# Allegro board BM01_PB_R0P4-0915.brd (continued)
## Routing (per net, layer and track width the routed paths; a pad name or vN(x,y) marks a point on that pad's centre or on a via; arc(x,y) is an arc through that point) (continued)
VCC5-20V_SYS: length 1.8
  BOTTOM w0.203: R623.2 26.99,2.69 27.42,3.12 v4(27.42,4.14)
  vias: v5(26.51,7.89) v5(26.51,7.25) v5(27.12,7.89) v5(27.12,7.25) v5(27.73,7.89) v5(27.73,7.25)
VCC5-20V_SYS_X1: length 5.5
  TOP w0.254: v1(23.83,14.24) 23.78,14.19 R701.1 23.63,14.19 v1(23.58,14.24)
  GND2 w0.254: v1(27.42,13.69) v1(27.17,13.69) 26.99,13.69 v2(26.86,13.56) ; v2(23.98,13.93) 23.83,14.07 v1(23.83,14.24) v1(23.58,14.24)
  GND5 w0.254: v3(26.27,13.51) v3(26.52,13.51) 26.81,13.51 v2(26.86,13.56) ; v2(23.98,13.93) 24.09,13.81 v3(24.09,13.51) v3(23.84,13.51)
  BOTTOM w0.254: v3(23.84,13.51) v3(24.09,13.51) v3(26.27,13.51) v3(26.52,13.51)
VCC5-20V_SYS_X2: length 4.8
  TOP w0.254: C712.1 16.24,5.21 15.98,4.95 R709.1 ; v1(12.83,6.88) v1(12.83,7.13) 12.88,7.19 R706.1
  GND2 w0.254: v2(13.15,6.97) 13.06,6.88 v1(12.83,6.88) v1(12.83,7.13) ; v1(15.9,6.81) v1(15.65,6.81) 15.59,6.75 v2(15.33,6.75)
  SIG4 w0.254: v2(15.33,6.75) 15.1,6.75 14.67,7.19 13.36,7.19 v2(13.15,6.97)
VCC5-20V_SYS_X3: length 8.3
  TOP w0.254: R710.1 v1(18.04,15.53) v1(17.79,15.53)
  GND2 w0.254: v2(22.08,14.49) 22.04,14.54 v1(21.76,14.54) v1(21.51,14.54) ; v1(17.79,15.53) v1(18.04,15.53) 18.19,15.53 18.21,15.54 v2(18.36,15.54)
  SIG3 w0.254: v2(22.08,14.49) 22,14.58 21.07,14.58 20.81,14.83 20.81,15.6 20.06,16.35 19.31,16.35 18.5,15.54 v2(18.36,15.54)
  GND5 w0.254: v3(22.41,14.96) v3(22.24,14.78) 22.08,14.63 v2(22.08,14.49)
  BOTTOM w0.254: R714.1 22.5,15.04 v3(22.41,14.96) v3(22.24,14.78)
VCC_0V9:
  vias: v5(14.8,18.56) v5(15.44,18.56) v5(16.07,18.56) v5(35.65,18.6) v5(36.26,18.6)
VCC_0V9_X1: length 5.6
  TOP w0.254: 18.29,18.02 17.04,16.77 17.04,14.58 18.12,13.5 R711.2
VCC_0V9_X2: length 5.9
  TOP w0.254: C722.2 v1(18.27,16.13) v1(18.02,16.13)
  GND2 w0.254: v2(21.4,15.19) 21.52,15.07 v1(21.72,15.07) v1(21.97,15.07) ; v1(18.02,16.13) v1(18.27,16.13) v2(18.27,16.46)
  SIG4 w0.254: v2(18.27,16.46) 18.68,16.87 20.24,16.87 21.4,15.72 v2(21.4,15.19)
VCC_3V3_SYS1: length 88.5
  TOP w0.254: v4(50.05,13.28) 50.05,12.93 48.73,11.61 45.86,11.61 45.25,12.22 R1112.1
  SIG3 w0.254: v5(37.17,19.54) 37.82,19.54 42.53,14.83 47.94,14.83 48.65,14.12 49.21,14.12 v4(50.05,13.28) 50.05,12.95 49.35,12.25 49.35,7.05 47.54,5.23 44.61,5.23 43.17,3.78 40.87,3.78 39.86,4.79 39.86,5.18 39.58,5.47 v2(39.14,5.47) 38.8,5.81 37.74,5.81 36.89,6.67 36.89,7.9 35.03,9.76 28.51,9.76 v2(28.11,9.37)
  SIG3 w0.305: v4(6.25,15.65) 6.88,15.02 v4(9.42,15.02)
  SIG4 w0.254: v2(22.85,16.43) 22.85,16.63 21.91,17.57 21.91,20.11 22.06,20.27 v5(22.06,20.53) v5(21.43,20.53)
  SIG4 w0.305: v5(21.43,20.53) 21.13,20.53 20.89,20.29 12.69,20.29 10.07,17.67 10.07,15.47 9.62,15.02 v4(9.42,15.02)
  GND5 w0.254: v3(23.06,16.03) 22.9,16.03 22.83,16.1 v3(22.82,16.1) 22.82,16.4 v2(22.85,16.43)
  GND5 w0.305: v3(38.81,5.47) v2(39.14,5.47) ; v3(28.11,9.95) v3(28.11,9.7) v2(28.11,9.37)
  BOTTOM w0.254: C804.1 v4(6.25,15.65) ; C804.1 R801.2 R803.1 ; C804.1 6.71,16.22 6.81,16.32 U801.A3 ; R525.1 v3(38.81,5.47) R524.1 ; R802.1 v4(9.42,15.02) ; v3(22.82,16.1) 22.89,16.03 v3(23.06,16.03) R908.1
  BOTTOM w0.305: R518.1 27.19,12.19 27.37,12.19 27.57,11.99 27.33,11.75 R526.1 27.13,11.72 26.83,11.41 26.83,10.21 27.45,9.59 28,9.59 v3(28.11,9.7) v3(28.11,9.95) R527.1
  vias: v5(36.56,19.54)
VCC_3V3_SYS1_X1: length 8.1
  TOP w0.254: R703.2 23.59,11.61 22.86,12.34 v1(22.86,13.42) v1(22.86,13.67)
  GND2 w0.254: v1(22.86,13.42) v1(22.86,13.67) 23.09,13.9 v2(23.1,13.9) ; v1(24.88,16.47) v1(25.13,16.47) v2(25.13,16.14)
  SIG3 w0.254: v2(25.13,16.14) 25.13,15.11 24.58,14.56 23.47,14.56 23.1,14.2 v2(23.1,13.9)
VCC_3V3_SYS1_X2: length 5.5
  TOP w0.254: v1(24.11,15.36) 24.35,15.36 C704.2
  GND2 w0.254: v2(26.91,14.5) 27.09,14.32 v1(27.19,14.32) v1(27.44,14.32) ; v1(24.36,15.36) v1(24.11,15.36) 24.11,15.08 v2(24.06,15.03)
  GND5 w0.254: v2(26.91,14.5) 26.86,14.5 v3(26.66,14.3) v3(26.4,14.3) ; v2(24.06,15.03) 24.07,15.02 v3(24.07,14.69) 24.07,14.6 v3(24.2,14.47)
  BOTTOM w0.254: v3(26.66,14.3) v3(26.4,14.3) 24.38,14.3 v3(24.2,14.47) 24.07,14.6 v3(24.07,14.69)
VDD12:
  vias: v5(12.85,18.56) v5(13.16,18.04) v5(13.48,18.56) v5(33.55,19.49) v5(34.16,19.49) v5(34.77,19.49)
VDD12_BST: length 1.1
  TOP w0.254: C713.1 13.77,8.11 14.06,7.81 U702.5
VDD12_EN: length 1.6
  TOP w0.254: U702.6 13.96,7.31 13.62,7.65 C716.1 R706.2
VDD12_FB: length 1.8
  TOP w0.254: U702.8 14.25,6.31 14,6.06 R708.2 R707.1
VDD12_PG: length 0.9
  TOP w0.254: U702.1 15.78,5.81 15.75,5.78 R709.2
VDD12_SS: length 1.2
  TOP w0.254: U702.7 13.98,6.81 13.44,6.28 C718.1
VDD12_X1: length 6.8
  TOP w0.254: 13.54,10.45 13.13,10.45 11.57,8.89 11.57,6.67 R707.2
VDD12_X2: length 5.1
  TOP w0.254: v1(12.34,7.72) 12.34,7.72 v1(12.52,7.91) 12.72,8.11 C713.2
  GND2 w0.254: v2(12.27,7.39) 12.27,7.65 v1(12.34,7.72) 12.34,7.72 v1(12.52,7.91) ; v1(15.9,7.36) v1(15.65,7.36) 15.35,7.36 v2(15.32,7.36)
  SIG3 w0.254: v2(12.27,7.39) 12.43,7.55 15.13,7.55 v2(15.32,7.36)
90_BILLBOARD_DN_X1: length 8.5
  SIG3 w0.089: v4(4.27,11.22) 4.11,11.38 3.88,11.38 3.67,11.59 3.67,12.07 4.01,12.41 5.12,12.41 5.83,11.71 6.02,11.71 v4(6.15,11.83)
  BOTTOM w0.102: J801.A7 5.63,11.75 5.77,11.61 5.93,11.61 v4(6.15,11.83) 6.29,11.68 6.97,11.68 7.04,11.75 7.32,11.75 TVS806.2 7.58,11.73 7.8,11.73 R810.2 ; v4(4.27,11.22) 4.74,10.75 J801.B7
90_BILLBOARD_DN_X2: length 36.9
  TOP w0.102: J1002.11 34.61,4.2 34.51,4.1 34.31,4.1 34.21,4.2 v4(34.21,4.31)
  SIG3 w0.089: v4(8.94,11.93) 8.94,11.82 9.03,11.73 9.35,11.73 9.65,11.43 9.65,5.55 10.8,4.4 17.69,4.4 19.86,2.23 33.1,2.23 33.63,2.76 33.63,3.89 33.84,4.1 34.01,4.1 v4(34.21,4.31)
  BOTTOM w0.102: R810.1 8.56,11.73 8.74,11.73 v4(8.94,11.93)
90_BILLBOARD_DP_X1: length 8.5
  SIG3 w0.089: v4(6.15,11.22) 6.15,11.32 5.96,11.5 5.74,11.5 5.57,11.68 5.44,11.68 5.37,11.61 5.24,11.61 5.12,11.73 5.12,11.86 5.19,11.93 5.19,12.06 5.04,12.21 4.09,12.21 3.87,11.99 3.87,11.67 3.96,11.58 4.16,11.58 4.27,11.68 v4(4.27,11.83)
  BOTTOM w0.102: J801.B6 4.69,12.25 v4(4.27,11.83) ; J801.A6 5.63,11.25 5.79,11.41 5.96,11.41 v4(6.15,11.22) 6.4,11.48 7.06,11.48 7.12,11.55 7.28,11.55 TVS805.2 7.58,11.53 7.8,11.53 R811.2
90_BILLBOARD_DP_X2: length 36.9
  TOP w0.102: v4(34.21,3.7) 34.21,3.8 34.31,3.9 34.51,3.9 34.61,3.8 J1002.12
  SIG3 w0.089: v4(8.94,11.32) 9.14,11.53 9.27,11.53 9.45,11.35 9.45,5.47 10.72,4.2 17.6,4.2 19.78,2.02 33.18,2.02 33.84,2.67 33.84,3.81 33.93,3.9 34.08,3.9 34.21,3.77 v4(34.21,3.7)
  BOTTOM w0.102: v4(8.94,11.32) 8.74,11.53 8.56,11.53 R811.1
C_PD_ADA_VBUS1: length 0.9
  TOP w0.254: v5(8.38,8.12) R1001.2
  vias: v5(3.61,14.27) v5(3.61,13.64) v5(3.61,9.63) v5(3.61,9) v5(4.24,14.27) v5(4.24,13.64) v5(4.24,9.63) v5(4.24,9) v5(6.48,8.73) v5(6.48,8.12) v5(7.11,8.73) v5(7.11,8.12) v5(7.75,8.73) v5(7.75,8.12) v5(8.38,8.73)
CHARGE_OC: length 31.9
  GND2 w0.109: v1(31.82,5.88) 31.88,5.81 v2(32.14,5.81)
  SIG4 w0.109: v2(32.14,5.81) 32.76,6.44 35.38,6.44 35.75,6.8 35.75,14.3 38.15,16.7 38.15,19.9 37.35,20.71 25.68,20.71 v2(25.46,20.93)
  GND5 w0.109: v2(25.46,20.93) 25.43,20.96 v3(25.13,20.96)
CHARGE_PE1: length 36.1
  GND2 w0.109: v1(30.81,5.94) 30.94,5.81 v2(31.12,5.81)
  SIG4 w0.109: v2(31.12,5.81) 31.97,6.67 35.29,6.67 35.52,6.9 35.52,14.39 37.92,16.79 37.92,19.8 37.25,20.47 30.31,20.47 26.5,16.66 v2(24.19,16.66)
  GND5 w0.109: v2(24.19,16.66) 24.24,16.61 v3(24.52,16.61)
  BOTTOM w0.254: R902.2 24.75,16.79 24.86,16.9 U901.1
CHG_CC1: length 40.3
  TOP w0.305: J1002.9 35.61,4.5 v4(35.39,4.28)
  SIG3 w0.305: v4(35.39,4.28) 34.77,4.9 23.99,4.9 20.57,8.32 12.16,8.32 10.89,9.59 10.89,14.81 9.21,16.49 v4(5.74,16.49)
  BOTTOM w0.254: v4(5.74,16.49) 6.32,16.49 6.67,16.85 U801.A2
CHG_CC2: length 42.9
  TOP w0.305: J1002.7 36.61,4.89 36.27,4.55 v4(36.16,4.55)
  SIG3 w0.305: v4(6.53,17.69) 6.53,18.08 7.15,18.69 9.91,18.69 11.32,17.28 11.32,9.77 12.34,8.75 20.75,8.75 24.17,5.33 35.38,5.33 v4(36.16,4.55)
  GND5 w0.254: v3(7.21,16.85) 7.01,17.05 7.01,17.26 6.58,17.69 v4(6.53,17.69)
CHG_VBUS_MON: length 32.9
  TOP w0.254: v1(11.87,5.41) v1(11.62,5.41) 9.87,5.41 8.9,6.38 R1001.1 R1002.2
  TOP w0.381: J1002.5 37.61,4.83 36.95,4.17 v4(36.6,4.17)
  GND2 w0.254: v1(11.62,5.41) v1(11.87,5.41) 12.03,5.57 v2(12.03,5.7)
  SIG4 w0.305: v2(12.03,5.7) 12.21,5.52 22.71,5.52 23.16,5.08 36.38,5.08 36.69,4.77 36.69,4.25 v4(36.6,4.17)
DSP_AUX_CTR: length 3.1
  BOTTOM w0.175: U801.D3 8.43,16.04 C805.1 R804.1 R802.2 R809.1 8.55,14.42 Q801.3
DSP_CC1_X1: length 15.5
  SIG4 w0.254: v4(6.17,17) 6.2,16.98 6.2,16.35 6.7,15.84 6.7,15.47 6.47,15.23 6.47,12.69 7.29,11.87 7.29,10.39 7.77,9.91 8.46,9.91 v2(8.84,10.3)
  GND5 w0.254: v2(8.84,10.3) v3(8.51,10.3) v3(8.51,10.04)
  BOTTOM w0.203: TP801.1 5.41,17.76 v4(6.17,17) 6.42,17.25 U801.A1
  BOTTOM w0.254: J801.A5 5.73,10.25 5.8,10.18 6.96,10.18 7.23,10.45 TVS807.2 8.35,10.45 v3(8.51,10.3) v3(8.51,10.04)
DSP_CC2_X1: length 12.4
  SIG4 w0.254: v2(6.96,13.83) 6.85,13.94 6.85,15.07 7.01,15.24 7.32,15.24 7.74,14.82 8.01,14.82 8.2,15.01 8.2,16.66 8.01,16.85 7.65,16.85 7.49,16.7 7.49,16.33 7.29,16.12 6.96,16.12 6.63,16.46 6.63,17.14 7.02,17.54 v4(7.02,17.89)
  GND5 w0.254: v2(6.96,13.83) 6.96,13.59 v3(6.88,13.51) 6.88,13.43 v3(6.74,13.29)
  BOTTOM w0.203: U801.B1 7.21,17.44 7.02,17.63 v4(7.02,17.89) 6.62,18.3 TP802.1
  BOTTOM w0.254: J801.B5 6.06,13.25 6.07,13.24 TVS802.2 6.69,13.24 v3(6.74,13.29) 6.88,13.43 v3(6.88,13.51)
DSP_SBU1_X1: length 13.6
  SIG4 w0.254: v2(7.96,10.37) 7.67,10.66 7.67,12.03 6.99,12.71 6.99,13.16 8.58,14.75 8.58,16.88 8.23,17.23 7.97,17.23 7.56,17.63 v4(7.56,17.69)
  GND5 w0.254: v2(7.96,10.37) 7.86,10.28 v3(7.86,10.06) v3(8.11,10.06)
  BOTTOM w0.203: U801.C1 7.56,17.3 v4(7.56,17.69)
  BOTTOM w0.254: J801.B8 6.03,9.75 6.09,9.8 7.13,9.8 7.23,9.91 TVS804.2 7.72,9.91 v3(7.86,10.06) v3(8.11,10.06) ; R807.1 v4(7.56,17.69)
DSP_SBU1_X2: length 2.3
  GND5 w0.254: v3(7.61,16.85) 7.61,17.02 8.16,17.57 v4(8.16,17.69)
  BOTTOM w0.254: v4(8.16,17.69) 8.38,17.92 R807.2 R812.2
DSP_SBU1_X3: length 39.4
  TOP w0.102: J1002.16 32.61,2.8 32.21,3.2 32.21,3.44 32.31,3.54 v4(32.42,3.54)
  SIG3 w0.089: v4(8.99,12.78) 9.13,12.92 9.35,12.92 10.13,12.15 10.13,9.28 10.46,8.94 10.46,5.84 11.45,4.86 18.38,4.86 20.55,2.69 31.83,2.69 32.26,3.12 32.26,3.38 v4(32.42,3.54)
  BOTTOM w0.102: v4(8.99,12.78) 9.17,12.96 9.52,12.96 10.04,13.48 10.04,17.37 9.77,17.64 9.77,17.85 9.5,18.12 R812.1
DSP_SBU2_X1: length 9.8
  SIG4 w0.254: v2(7.47,12.99) 8.96,14.48 8.96,17.3 9.32,17.66 v4(9.32,17.74)
  GND5 w0.254: v2(7.47,12.99) 7.47,12.94 v3(7.26,12.73) v3(7,12.73)
  BOTTOM w0.203: v4(9.32,17.74) 9.32,17.66 9.09,17.44 R808.1 8.6,17.44 8.41,17.25 U801.D1
  BOTTOM w0.254: J801.A8 5.78,12.75 5.88,12.85 6.31,12.85 6.41,12.76 TVS803.2 6.96,12.76 6.99,12.73 v3(7,12.73) v3(7.26,12.73)
DSP_SBU2_X2: length 1.7
  BOTTOM w0.175: U801.D2 8.28,16.85 8.51,16.62 R808.2 9.31,16.62 R813.2
DSP_SBU2_X3: length 39.3
  TOP w0.102: v4(31.81,3.54) 31.91,3.54 32.01,3.44 32.01,3.21 31.61,2.82 J1002.18
  SIG3 w0.089: v4(8.99,13.39) 8.99,13.28 9.14,13.13 9.44,13.13 10.33,12.23 10.33,9.36 10.67,9.03 10.67,8.77 10.76,8.69 10.81,8.69 10.9,8.6 10.9,8.42 10.81,8.33 10.76,8.33 10.67,8.24 10.67,8.06 10.76,7.97 10.81,7.97 10.9,7.88 10.9,7.71 10.81,7.62 10.76,7.62 10.67,7.53 10.67,7.35 10.76,7.26 10.81,7.26 10.9,7.17 10.9,7 10.81,6.91 10.76,6.91 10.67,6.82 10.67,6.64 10.76,6.55 10.81,6.55 10.9,6.46 10.9,6.28 10.81,6.2 10.76,6.2 10.67,6.11 10.67,5.93 11.53,5.06 18.47,5.06 20.63,2.9 31.74,2.9 32.05,3.21 32.05,3.46 31.97,3.54 v4(31.81,3.54)
  BOTTOM w0.102: R813.1 9.5,17.27 9.6,17.37 9.75,17.37 9.84,17.28 9.84,13.57 9.44,13.16 9.09,13.16 8.99,13.26 v4(8.99,13.39)
EN2: length 2.6
  TOP w0.107: U1101.C1 43.2,13.96 43.64,13.52 R1111.2 R1110.2
GPIO1_ILIMT_2A: length 26.7
  TOP w0.107: v4(48.93,14.87) 48.93,14.37 47.44,12.88 46.57,12.88 R1105.2
  GND2 w0.127: v2(34.07,5.81) 34.01,5.81 v1(33.81,5.61)
  SIG4 w0.109: v2(34.07,5.81) 34.19,5.94 35.56,5.94 36.22,6.61 36.22,12.82 38.47,15.07 48.74,15.07 v4(48.93,14.87)
GPIO2_CHG_VBUS_DISCHARGE: length 41.3
  TOP w0.109: v4(38.35,3.87) 38.08,4.14 38.08,4.55 38.61,5.08 J1002.3
  SIG3 w0.109: v2(15.42,16.38) 15.28,16.52 13.11,16.52 12.13,15.55 12.13,10.1 12.68,9.55 21.09,9.55 24.5,6.14 29.7,6.14 30.23,6.67 35.31,6.67 38.12,3.87 v4(38.35,3.87)
  GND5 w0.109: v3(15.62,16.65) 15.42,16.45 v2(15.42,16.38)
  BOTTOM w0.109: R603.2 15.83,16.86 v3(15.62,16.65)
GPIO4_CHG_VBUS_CTRL: length 54
  TOP w0.109: v4(38.63,3.41) 38.61,3.4 J1002.4
  SIG3 w0.109: v4(38.63,3.41) 38.24,3.41 35.22,6.44 30.35,6.44 29.82,5.9 24.4,5.9 20.99,9.32 12.58,9.32 11.89,10 11.89,15.64 13.01,16.76 16.07,16.76 16.86,15.97 v2(17.35,15.97)
  SIG4 w0.109: v2(17.35,15.97) 17.35,16.57 17.03,16.89 12.84,16.89 10.44,14.49 v4(9.42,14.49)
  GND5 w0.109: v2(17.35,15.97) v3(17.68,15.97)
  BOTTOM w0.109: R604.2 17.88,15.77 v3(17.68,15.97) ; v4(9.42,14.49) 9.39,14.51 R809.2 R805.2
GPIO4_CTRL_X1: length 2.9
  BOTTOM w0.175: Q801.1 7.77,15.02 7.4,14.64 R803.2 R806.1 7.29,14 R805.1
GPIO5_PLUG_VBUS_DISCHARGE: length 65.5
  TOP w0.109: J1002.1 39.61,5.08 39.24,4.7 v4(38.52,4.38) ; R605.1 16.21,15.74 v1(16.16,15.79) ; v4(50.05,12.27) 50.05,12.09 49.26,11.3 45.5,11.3 R1109.1
  GND2 w0.109: v2(16.16,16.12) v1(16.16,15.79)
  SIG3 w0.109: v2(16.16,16.12) 16.02,15.97 15.2,15.97 14.89,16.29 13.21,16.29 12.37,15.45 12.37,10.2 12.78,9.79 21.18,9.79 24.6,6.37 29.55,6.37 30.09,6.91 35.41,6.91 37.93,4.38 v4(38.52,4.38) 38.69,4.56 39.66,4.56 40.76,3.45 43.42,3.45 44.79,4.82 47.64,4.82 49.66,6.85 49.66,11.88 v4(50.05,12.27)
GPIO6_PLUG_VBUS_CTRL: length 44.4
  TOP w0.109: v4(39.5,3.41) 39.61,3.3 J1002.2
  SIG3 w0.109: v2(16.87,16.5) 16.38,17 12.91,17 11.66,15.74 11.66,9.91 12.48,9.08 20.89,9.08 24.3,5.67 29.99,5.67 30.52,6.2 35.12,6.2 38.29,3.03 39.12,3.03 v4(39.5,3.41)
  GND5 w0.109: v3(16.81,16.83) 16.81,16.56 v2(16.87,16.5)
GPIO7_KS1865C_EN: length 32.2
  TOP w0.107: v1(34.12,1.64) 31.08,1.64 30.61,2.1 J1002.20 ; v4(50.05,10.23) 49.45,10.83 45,10.83 R1110.1
  GND2 w0.127: v1(34.12,1.64) v2(34.35,1.87)
  SIG4 w0.109: v2(34.35,1.87) 34.85,2.36 42.56,2.36 44.23,4.04 47.46,4.04 50.05,6.63 v4(50.05,10.23)
GPIO8_ILIMT_3A: length 27
  TOP w0.107: R1106.2 47.35,13.2 48.53,14.37 48.53,15.09 v4(48.93,15.49)
  GND2 w0.127: v1(32.78,5.61) 32.98,5.81 v2(33.04,5.81)
  SIG4 w0.109: v4(48.93,15.49) 48.74,15.3 38.33,15.3 35.99,12.96 35.99,6.7 35.48,6.2 33.42,6.2 v2(33.04,5.81)
HV_AGND1: length 5.4
  GND5 w0.254: v3(37.34,5.47) v3(37.59,5.47) 37.59,6.08 v2(37.86,6.35) ; v2(40.35,5.13) 40.29,5.19 40.29,5.42 v3(40.22,5.48) ; v3(40.35,12.39) v2(40.12,12.16)
  BOTTOM w0.254: U501.17 v3(40.35,12.39) ; R514.2 v3(37.34,5.47) v3(37.59,5.47) ; v4(42.6,6.03) 42.52,5.95 C512.2 R509.1 ; v4(42.6,6.59) 42.47,6.46 C511.1 R507.1 ; C510.1 41.07,13.9 40.87,14.11
  vias: v2(38.99,13.97) v2(39.27,14.26) v3(38.8,14.24) v3(38.98,14.41) v3(39.15,14.59) v3(39.4,14.57)
I2C0_SCL_X1: length 19.8
  TOP w0.109: J1002.8 v4(36.61,3.4)
  SIG3 w0.109: v2(28.79,9.28) 29.03,9.04 35.07,9.04 36.36,7.75 36.36,6.63 37.54,5.45 38.48,5.45 38.93,5 v2(39.41,5)
  SIG4 w0.109: v2(39.41,5) 39.39,5.01 38.29,5.01 37.62,4.33 37.62,3.25 37.39,3.02 36.99,3.02 v4(36.61,3.4)
  GND5 w0.127: v2(39.41,5) 39.62,5.21 v3(39.62,5.26) ; v3(28.61,9.59) 28.61,9.46 v2(28.79,9.28)
  BOTTOM w0.107: R520.2 v3(39.62,5.26) ; R523.1 v3(28.61,9.59)
I2C0_SDA_X1: length 17.6
  TOP w0.109: v4(37.23,3.41) 37.61,3.03 J1002.6
  SIG3 w0.109: v2(37.81,5.06) 37.59,5.06 36.11,6.55 36.11,7.67 34.97,8.8 28.13,8.8 27.42,9.51 v2(27.42,9.83)
  SIG4 w0.109: v4(37.23,3.41) 37.38,3.56 37.38,4.64 v2(37.81,5.06)
  GND5 w0.127: v3(27.7,9.99) 27.58,9.99 v2(27.42,9.83) ; v2(37.81,5.06) 38.08,5.34 v3(38.08,5.35)
  BOTTOM w0.107: v3(38.08,5.35) 38.1,5.36 R521.2 ; v3(27.7,9.99) 27.34,10.35 R522.1
MOUT: length 1.8
  BOTTOM w0.254: 21.25,7.26 21.14,7.16 R615.2 ; 18.36,9.54 18.17,9.54 R607.1
MOUT_ADC: length 8.2
  TOP w0.107: J1002.14 33.61,2.9 v1(33.31,3.2)
  GND2 w0.127: v2(33.03,3.04) 33.19,3.2 v1(33.31,3.2)
  GND5 w0.127: v2(33.03,3.04) v3(32.79,2.8)
  BOTTOM w0.107: R625.1 31.99,2 v3(32.79,2.8)
MT7231_DISCI: length 0.8
  BOTTOM w0.254: R620.2 21.56,4.65 21.68,4.78 U602.2
MT7231_DISCO: length 0.9
  BOTTOM w0.254: R616.2 21.46,5.31 21.52,5.38 U602.3
MT7231_EN: length 0.8
  BOTTOM w0.254: U602.4 R615.1
MT7231_FLTB: length 0.9
  BOTTOM w0.254: U602.9 24.57,6.58 24.92,6.23 R619.2
MT7231_ILIM: length 1.4
  BOTTOM w0.254: U602.11 24.61,5.38 24.77,5.21 C616.1 R621.2
MT7231_MOUT: length 8.3
  SIG3 w0.305: v2(25.49,6.89) 25.18,6.89 v4(23.41,8.66)
  GND5 w0.305: v2(25.49,6.89) v3(25.49,6.48) v3(25.49,6.23)
  BOTTOM w0.175: v4(23.41,8.66) 23.12,8.38 U602.7
  BOTTOM w0.203: U602.15 U602.7
  BOTTOM w0.254: v3(25.49,6.23) v3(25.49,6.48)
MT7231_NOSS: length 0.9
  BOTTOM w0.254: R617.2 21.41,3.99 21.59,4.18 U602.1
MT7231_VLIM: length 1.2
  BOTTOM w0.254: R622.2 24.96,4.28 24.47,4.78 U602.12
MT7232_DISC1: length 2.3
  TOP w0.254: v4(15.51,14.12) 15.51,14.01 15.91,13.61 R610.2 R605.2
  BOTTOM w0.254: U601.2 15.51,13.61 v4(15.51,14.12)
MT7232_DISC2: length 3.2
  BOTTOM w0.254: 16.13,13.96 U601.3
  BOTTOM w0.305: 16.13,13.96 16.03,14.06 R609.2 15.74,14.55 15.49,14.8 15.49,15.7 15.83,16.04 R603.1
MT7232_EN1: length 3.2
  BOTTOM w0.254: 16.73,13.97 U601.4
  BOTTOM w0.305: R606.2 17.04,16.04 17.33,15.75 17.33,14.78 17.1,14.55 R611.2 16.79,14.03 16.73,13.97
MT7232_EN2: length 2.2
  BOTTOM w0.254: U601.5 17.33,13.76
  BOTTOM w0.305: R608.2 R604.1 17.88,14.53 17.33,13.98 17.33,13.76
MT7232_FLTB: length 1
  BOTTOM w0.254: U601.9 17.33,11.08 17.66,10.74 R607.2
MT7232_ILIM1: length 1.4
  BOTTOM w0.254: R612.2 C607.1 16.03,10.81 16.13,10.91 U601.11
MT7232_ILIM2: length 1.5
  TOP w0.254: v4(14.98,14.12) R613.2 C608.1
  BOTTOM w0.254: v4(14.98,14.12) 14.98,14.11 14.93,14.05 U601.1
MT7232_VLIM: length 0.8
  BOTTOM w0.254: R614.2 U601.12
OVLO: length 1.5
  BOTTOM w0.254: U901.2 24.21,16.86 24.12,16.76 R904.1 R910.2
OVLO_17839094: length 1.7
  TOP w0.107: R1113.1 R1114.2 44.47,15.71 44.23,15.96 U1101.D5
PD_USP_VBUS: length 4.6
  TOP w0.254: v4(45.12,17.43) R1113.2
  GND2 w0.254: v2(42.68,16.79) v1(42.68,17.13) v1(42.68,17.38)
  SIG4 w0.254: v2(42.68,16.79) 44.68,16.79 45.12,17.23 v4(45.12,17.43)
PD_USP_VBUS_X1:
  vias: v5(13.09,15.18) v5(13.09,14.54) v5(13.09,13.91) v5(13.73,15.18) v5(13.73,14.54) v5(13.73,13.91) v5(30.14,13.94) v5(30.14,13.33) v5(30.75,13.94) v5(30.75,13.33) v5(31.36,13.94) v5(31.36,13.33)
PP5V0: length 2.3
  BOTTOM w0.254: v3(21.64,19.03) 21.22,18.61 R905.2
  vias: v2(22.72,19.77) v2(22.72,19.37) v2(23.12,19.77) v2(23.12,19.37) v2(25.72,18.88) v2(26.12,18.88) v2(26.54,19.29) v2(26.54,18.88) v3(21.64,19.53) v3(21.64,19.28) v3(21.89,19.53) v3(21.89,19.28) v3(21.89,19.03) v3(22.14,19.53) v3(22.14,19.28) v3(22.14,19.03) v3(22.39,19.53) v3(22.39,19.28) v3(22.39,19.03) v3(25.46,19.67) v3(25.46,19.42) v3(25.46,19.17) v3(25.71,19.71) v3(25.71,19.46) v3(25.71,19.21) v3(25.96,19.69) v3(25.96,19.44) v3(25.96,19.19) v3(26.21,19.7) v3(26.21,19.45) v3(26.21,19.2) v4(23.24,18.61) v4(23.82,18.61) v4(24.41,18.61) v4(24.99,18.61) v5(30.47,19.61) v5(30.47,19) v5(30.47,18.39) v5(31.08,19.61) v5(31.08,19) v5(31.08,18.39)
PP5V0_SYS: length 1.6
  SIG4 w0.254: 23.74,16.94 23.74,16.37 v2(23.86,16.24)
  GND5 w0.254: v2(23.86,16.24) 24.1,16 v3(24.12,16) v3(24.12,15.75)
  BOTTOM w0.254: v3(24.12,15.75) v3(24.12,16) R904.2
  vias: v2(22.86,17.62) v2(23.27,17.62) v2(25.27,18.1) v2(25.68,18.1) v2(26.09,18.1) v2(26.49,18.1) v3(21.79,18.05) v3(21.79,17.8) v3(21.79,17.55) v3(22.04,18.05) v3(22.04,17.8) v3(22.04,17.55) v3(22.29,18.05) v3(22.29,17.8) v3(22.29,17.55) v3(22.54,18.05) v3(22.54,17.8) v3(22.54,17.55) v3(25.46,17.78) v3(25.46,17.53) v3(25.46,17.28) v3(25.71,17.78) v3(25.71,17.53) v3(25.71,17.28) v3(25.96,17.78) v3(25.96,17.53) v3(25.96,17.28) v3(26.21,17.78) v3(26.21,17.53) v3(26.21,17.28) v4(22.99,18.11) v4(23.57,18.11) v4(24.15,18.11) v4(24.74,18.11) v5(34.25,18.6) v5(34.86,18.6)
PW_5V_BOOT1: length 0.8
  BOTTOM w0.254: U501.20 41.49,7.95 41.53,7.99 C505.2
PW_5V_BOOT2: length 0.8
  BOTTOM w0.254: U501.19 41.35,11.03 41.47,11.15 C506.2
PW_5V_CDC: length 1.6
  BOTTOM w0.254: U501.16 39.85,12.23 39.33,12.74 R516.2
PW_5V_COMP: length 2.1
  BOTTOM w0.254: R517.2 C521.1 38.82,12.67 39.35,12.14 U501.15
PW_5V_DITH: length 1.8
  BOTTOM w0.254: U501.5 38.04,7.29 38.04,6.48 37.59,6.03 C519.2
PW_5V_EN: length 3
  BOTTOM w0.254: R508.2 R509.2 C512.1 41.28,5.95 40.35,6.87 U501.1
PW_5V_EXTVCC: length 1.8
  BOTTOM w0.254: U501.21 41.3,7.45 41.33,7.48 R504.1 R507.2 C511.2
PW_5V_FB: length 2.3
  BOTTOM w0.254: U501.14 38.85,12.06 37.81,13.1 R515.2 R511.1
PW_5V_FSW: length 2.6
  BOTTOM w0.254: U501.6 37.97,7.95 37.66,7.64 37.66,6.64 37.08,6.06 R514.1
PW_5V_MODE: length 1.8
  BOTTOM w0.254: R503.1 R506.2 40.13,6.33 39.85,6.61 U501.2
PW_5V_OUT: length 2.6
  BOTTOM w0.102: R512.2 34.44,14.48 34.3,14.48 34.12,14.3 34.12,14.04 33.53,13.45 R510.1
  vias: v1(31.76,12.41) v1(31.76,12.16) v1(31.76,11.91) v1(31.76,11.66) v1(32.01,12.41) v1(32.01,12.16) v1(32.01,11.91) v1(32.01,11.66) v1(32.26,12.41) v1(32.26,12.16) v1(32.26,11.91) v1(32.26,11.66) v1(32.51,12.41) v1(32.51,12.16) v1(32.51,11.91) v1(32.51,11.66) v1(34.8,12.44) v1(34.8,12.19) v1(34.8,11.94) v1(34.8,11.69) v1(35.05,12.44) v1(35.05,12.19) v1(35.05,11.94) v1(35.05,11.69) v1(35.3,12.44) v1(35.3,12.19) v1(35.3,11.94) v1(35.3,11.69) v1(35.55,12.44) v1(35.55,12.19) v1(35.55,11.94) v1(35.55,11.69) v2(32.85,12.29) v2(32.85,11.88) v2(33.26,12.29) v2(33.26,11.88) v2(33.66,12.29) v2(33.66,11.88) v2(34.07,12.29) v2(34.07,11.88) v2(34.47,12.29) v2(34.47,11.88) v3(31.91,12.05) v3(31.91,11.8) v3(31.91,11.55) v3(31.91,11.3) v3(32.16,12.05) v3(32.16,11.8) v3(32.16,11.55) v3(32.16,11.3) v3(32.41,12.05) v3(32.41,11.8) v3(32.41,11.55) v3(32.41,11.3) v3(32.66,11.55) v3(32.66,11.3) v3(32.91,11.55) v3(32.91,11.3) v3(33.16,11.55) v3(33.16,11.3) v3(33.41,11.55) v3(33.41,11.3) v3(33.66,11.55) v3(33.66,11.3) v3(33.91,11.55) v3(33.91,11.3) v3(34.16,11.55) v3(34.16,11.3) v3(34.41,11.55) v3(34.41,11.3) v3(34.66,11.55) v3(34.66,11.3)
PW_5V_SENSE_N: length 5.9
  BOTTOM w0.102: U501.13 38.18,11.53 38.03,11.38 37.93,11.38 37.83,11.48 37.83,12.23 36.95,13.12 36.95,14.36 36.64,14.67 36.64,14.82 36.42,15.04 C520.2 36.14,15.04 35.83,14.73 35.59,14.73 35.49,14.83 R513.1
PW_5V_SENSE_P: length 5.7
  BOTTOM w0.102: U501.12 38.18,11.03 38.03,11.18 37.85,11.18 37.63,11.4 37.63,12.14 36.74,13.03 36.74,14.27 36.64,14.38 36.44,14.38 C520.1 36.14,14.22 35.83,14.52 35.59,14.52 35.49,14.42 R512.1
PW_5V_VCC: length 14.3
  SIG4 w0.254: v2(41.13,5.21) 42.15,4.19 42.93,4.19 43.34,4.61 43.34,6.53 v4(42.61,7.26) 43.34,8 43.34,10.98 v2(41.58,12.75)
  GND5 w0.305: v2(41.58,12.75) v3(41.16,12.75) v3(41.16,12.49) ; v2(41.13,5.21) 41.13,5.28 41.03,5.38 v3(40.94,5.47) v3(40.69,5.47)
  BOTTOM w0.254: R504.2 42.39,7.48 v4(42.61,7.26)
  BOTTOM w0.305: v3(40.94,5.47) v3(40.69,5.47) R503.2
PW_5V_VIN: length 6.7
  TOP w0.254: v4(42.57,4.94) 42.14,4.94 40.25,6.83 37.66,6.83 C532.1
  BOTTOM w0.254: R508.1 v4(42.57,4.94)
  vias: v1(31.54,7.69) v1(31.54,7.44) v1(31.79,7.69) v1(31.79,7.44) v1(32.04,7.69) v1(32.04,7.44) v1(32.29,7.69) v1(32.29,7.44) v1(32.54,7.69) v1(32.54,7.44) v1(34.45,7.69) v1(34.45,7.44) v1(34.7,7.69) v1(34.7,7.44) v1(34.95,7.69) v1(34.95,7.44) v1(35.2,7.69) v1(35.2,7.44) v2(32.89,8.23) v2(32.89,7.83) v2(32.89,7.42) v2(33.29,8.23) v2(33.29,7.83) v2(33.29,7.42) v2(33.7,8.23) v2(33.7,7.83) v2(33.7,7.42) v2(34.11,8.23) v2(34.11,7.83) v2(34.11,7.42) v3(31.55,7.34) v3(31.55,7.09) v3(31.8,7.34) v3(31.8,7.09) v3(32.05,7.34) v3(32.05,7.09) v3(32.3,7.34) v3(32.3,7.09) v3(32.55,7.34) v3(32.55,7.09) v3(32.8,7.09) v3(33.05,7.09) v3(33.3,7.09) v3(33.55,7.09) v3(33.8,7.09) v3(34.05,7.09) v3(34.3,7.09) v3(34.55,7.34) v3(34.55,7.09) v3(34.8,7.34) v3(34.8,7.09) v3(35.05,7.34) v3(35.05,7.09)
SBU_PROT_FLT: length 1.5
  BOTTOM w0.175: R801.1 7.22,15.15 7.61,15.54 U801.C3
STS2_ADD: length 2.5
  BOTTOM w0.229: U502.3 28.45,11.96 U502.5
  BOTTOM w0.305: R518.2 27.65,13.23 C524.1 C523.1 28.25,12.53 28.45,12.33 U502.5
TPS55289_I2C0_SCL_X1: length 1.8
  BOTTOM w0.107: R520.1 R524.2 39.12,6.31 39.35,6.54 U501.3
TPS55289_I2C0_SDA_X1: length 1.8
  BOTTOM w0.107: R521.1 R525.2 38.61,6.33 38.85,6.58 U501.4
TS2_SCL_X1: length 1.4
  BOTTOM w0.107: R523.2 R527.2 28.11,10.86 27.97,11.01 U502.2
TS2_SDA_X1: length 1.7
  BOTTOM w0.107: R522.2 R526.2 27.54,11.27 27.67,11.4 27.67,11.61 27.97,11.91 U502.4
N17338604: length 9.6
  BOTTOM w0.102: R510.2 33.53,14.55 33.68,14.4 33.94,14.4 34.22,14.68 34.33,14.68 R513.2
  BOTTOM w0.254: 31.6,15.73 31.79,15.54 36.84,15.54 37.3,15.08 R511.2
N17338820: length 0.5
  BOTTOM w0.254: C522.1 R517.1
N17369623: length 0.9
  BOTTOM w0.254: U602.10 24.59,5.98 24.86,5.7 C617.1
N17402193: length 1
  BOTTOM w0.254: C609.1 17.14,10.66 16.73,11.08 U601.10
N17646610: length 0.6
  TOP w0.254: R715.1 23.95,14.69 23.91,14.66 R704.1
N17828259: length 2.9
  BOTTOM w0.254: R909.2 R905.1 22.14,16.49 U901.4
N17829516: length 1.4
  BOTTOM w0.254: R908.2 23.1,16.66 23.33,16.89 23.5,16.89 23.76,17.15 U901.3
N17829521: length 1.7
  BOTTOM w0.107: R911.1 R907.2 24.33,19.8 24.21,19.68 U901.9
N17829622: length 0.9
  BOTTOM w0.381: R903.2 23,19.58 23.11,19.47 U901.7
N17839181: length 2.6
  TOP w0.107: R1104.2 45.39,15.23 R1103.2 R1102.2 44.49,15.23 44.27,15.46 U1101.D4
N17839251: length 0.9
  TOP w0.107: Q1102.3 46.42,15.73 R1104.1
N17839328: length 1.2
  TOP w0.107: R1105.1 R1107.2 45.84,13.81 Q1101.1
N17839336: length 1.2
  TOP w0.107: Q1102.1 46.86,13.81 R1108.2 R1106.1
N17850318: length 17.4
  TOP w0.107: v4(50.05,11.25) 49.86,11.06 45.23,11.06 44.64,11.65 R1109.2
  GND2 w0.127: v1(43.11,14.46) 43.84,15.19 45.07,15.19 v2(45.58,15.7)
  SIG4 w0.109: v2(45.58,15.7) 45.81,15.92 49.06,15.92 49.43,15.56 49.43,11.87 v4(50.05,11.25)
N17850490: length 0.9
  TOP w0.107: R1103.1 45.46,14.78 45.8,15.13 Q1101.3
N17851575: length 1.3
  BOTTOM w0.107: R624.2 R623.1 R625.2
N17873017: length 2.2
  TOP w0.107: R1112.2 44.41,12.44 44.31,12.44 43.88,12.88 43.88,13.69 U1101.D1
N178293080: length 0.7
  BOTTOM w0.254: C907.1 23.54,20.75 23.35,20.93 R903.1

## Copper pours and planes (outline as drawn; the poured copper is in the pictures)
GND on TOP: 44.69,26.96 58.5,26.96 63.09,22.36 63.09,-1.97 57.15,-7.92 48.62,-7.92 40.14,0.56 38.16,0.56 38.16,-2.82 33.05,-7.92 -5.46,-7.92 -9.78,-3.6 -9.78,17.43 -0.25,26.96 19.06,26.96 19.06,23.48 19.79,22.75 19.81,22.75 19.86,22.69 19.86,22.68 19.89,22.65 40.38,22.65 ; 81 cut-outs
GND on BOTTOM: 14.82,11.68 16.73,11.68 17.79,10.62 17.79,8.81 17.64,8.66 17.06,8.66 17.23,8.84 17.23,8.86 17.06,9.04 16.81,9.04 16.7,8.93 16.7,8.71 16.17,8.18 15.05,8.18 14.44,8.79 14.44,9.2 14.21,9.42 14.21,11.07
GND on BOTTOM: 44.22,26.53 56.82,26.53 61.72,21.62 61.72,0.01 55.47,-6.24 46.94,-6.24 40.31,0.39 39.39,0.39 38.35,-0.65 38.35,-4.54 36.65,-6.24 -2.72,-6.24 -8.66,-0.3 -8.66,18.25 -0.38,26.53 19,26.53 19,23.55 19.89,22.66 40.36,22.66 ; 121 cut-outs
GND on GND2: 46.68,28.91 61.24,28.91 68.5,21.65 68.5,4.05 57.07,-7.38 48.11,-7.38 40.28,0.44 39.42,0.44 39.42,-5.68 37.16,-7.94 -0.03,-7.94 -3.58,-4.39 -3.58,26.83 -1.5,28.91 17.98,28.91 17.98,24.52 19.76,22.75 19.81,22.75 19.86,22.69 19.86,22.64 19.99,22.51 40.28,22.51 ; 1 cut-out
GND on SIG3: 46.1,28.41 55.98,28.41 60.88,23.5 60.88,1.96 53.39,-5.53 46.23,-5.53 40.33,0.36 39.62,0.36 39.04,-0.22 39.04,-2.89 36.4,-5.53 -0.92,-5.53 -7.85,1.41 -7.85,16.95 3.61,28.41 18.72,28.41 18.72,23.83 19.89,22.66 40.36,22.66 ; 20 cut-outs
GND on SIG4: 45.24,27.49 55.85,27.49 60.38,22.97 60.38,1.07 52.96,-6.34 47.04,-6.34 40.39,0.31 38.56,0.31 38.48,0.24 38.48,-4.23 36.37,-6.34 6.25,-6.34 -2.13,2.04 -2.13,27.49 19,27.49 19,23.45 19.7,22.75 19.81,22.75 19.86,22.69 19.86,22.59 19.99,22.46 40.21,22.46 ; 14 cut-outs
GND on GND5: 44.6,26.88 54.48,26.88 65.53,15.83 65.53,4.76 54.38,-6.39 47.12,-6.39 40.26,0.47 38.84,0.47 38.84,-3.22 34.82,-7.23 -19.1,-7.23 -23.72,-2.61 -23.72,3.82 -0.66,26.88 18.9,26.88 18.9,23.66 19.94,22.61 40.33,22.61 ; 2 cut-outs
VCC5-20V_SYS on TOP: 21.68,8.03 25.39,8.03 26.37,9.01 28.87,9.01 28.99,8.89 28.99,4.16 28.77,3.94 21.81,3.94 21.52,4.23 21.52,7.87
VCC5-20V_SYS on BOTTOM: 24.59,9.97 26.03,9.97 27.05,8.95 28.61,8.95 28.87,8.68 28.87,6.81 28.82,6.76 27.83,6.76 27.67,6.6 27.67,6.04 27.57,5.94 26.07,5.94 25.49,6.53 23.87,6.53 23.79,6.45 23.79,3.73 23.75,3.69 23.49,3.69 23.47,3.72 23.47,8.11 24.48,9.12 24.48,9.86
VCC5-20V_SYS_X1 on TOP: 26.76,9.41 26.76,10.65 27.15,11.04 27.15,12.02 27.19,12.06 27.19,12.64 27.63,13.09 27.63,13.32 27.45,13.51 26.94,13.51 26.91,13.54 26.91,13.84 26.97,13.9 29.01,13.9 29.2,13.71 29.2,9.72 29.14,9.67 28.06,9.67 27.68,9.29 26.88,9.29
VCC5-20V_SYS_X2 on TOP: 16.16,5.15 16.16,6.24 15.9,6.51 15.6,6.51 15.44,6.66 15.44,6.94 15.5,6.99 20.65,6.99 20.85,6.79 20.85,5.09 20.72,4.95 16.36,4.95
VCC5-20V_SYS_X3 on TOP: 22.69,8.65 21.12,8.65 20.93,8.84 20.93,12.74 21.08,12.89 21.08,14.28 20.65,14.28 20.57,14.36 20.57,14.64 20.59,14.65 22.21,14.65 22.48,14.38 22.48,12.21 22.87,11.81 22.87,8.84
VCC_0V9 on TOP: 17.31,19.23 17.39,19.14 17.39,18.14 17.31,18.06 14.69,18.06 14.54,18.21 14.54,19.05 14.72,19.23
VCC_0V9 on TOP: 35.31,18.91 36.37,18.91 36.51,18.77 36.51,18.49 36.19,18.17 36.19,16.9 36.1,16.81 35.3,16.81 35.24,16.86 35.24,18.84
VCC_0V9 on SIG3: 21.03,19.44 22.95,17.52 23.18,17.52 23.51,17.85 26.63,17.85 26.96,17.52 34.2,17.52 35.61,18.93 36.3,18.93 36.51,18.72 36.51,17.14 34.45,15.09 25.64,15.09 25.31,15.42 25.31,16.15 24.88,16.15 24.85,16.13 24.85,15.57 24.37,15.09 22.39,15.09 19.42,18.06 14.87,18.06 14.54,18.39 14.54,19.15 14.83,19.44
VCC_0V9_X1 on TOP: 21.3,17.25 18.3,17.25 18.02,17.53 18.02,19.14 18.1,19.23 22.72,19.23 23.62,18.32 23.62,17.1 23.52,17 21.55,17
VCC_0V9_X2 on TOP: 23.38,14.78 20.68,14.78 20.59,14.88 20.59,15.21 20.61,15.24 21.25,15.24 21.37,15.36 21.37,15.64 21.53,15.8 23.58,15.8 23.61,15.77 23.61,15.01
VCC_3V3_SYS1 on TOP: 36.22,21.19 38.07,21.19 38.19,21.07 38.19,19.51 37.97,19.29 36.3,19.29 36.07,19.52 36.07,21.04
VCC_3V3_SYS1 on TOP: 21.38,20.86 23.01,20.86 23.22,20.65 23.22,19.6 23.01,19.39 21.39,19.39 21.16,19.62 21.16,20.64
VCC_3V3_SYS1 on SIG3: 37.14,21.21 37.72,20.63 37.72,19.39 37.61,19.28 36.46,19.28 35.5,20.24 29.65,20.24 28.99,19.58 24.88,19.58 24.4,20.06 21.32,20.06 21.16,20.23 21.16,20.76 21.5,21.11 24.83,21.11 25.28,20.65 27.93,20.65 28.49,21.21
VCC_3V3_SYS1_X1 on TOP: 24.66,16.34 30.11,16.34 30.11,17.47 30.01,17.57 26.86,17.57 26.33,18.11 26.33,19.58 25.15,20.76 23.98,20.76 23.85,20.63 23.85,19.66 24.6,18.9 24.6,16.41
VCC_3V3_SYS1_X2 on TOP: 27.67,15.72 27.67,14.65 27.47,14.45 26.91,14.45 26.87,14.41 26.87,14.05 26.9,14.03 29.36,14.03 30.16,14.83 30.16,15.85 27.8,15.85
VDD12 on TOP: 11.04,17.42 12.46,18.84 13.6,18.84 13.83,18.62 13.83,18.11 12.38,16.66 12.38,12.88 12.81,12.44 13.65,12.44 13.78,12.32 13.78,11.48 13.71,11.41 11.66,11.41 11.04,12.04
VDD12 on TOP: 33.3,21.19 34.98,21.19 35.08,21.09 35.08,19.42 34.9,19.24 33.43,19.24 33.22,19.44 33.22,21.12
VDD12 on SIG4: 26,15.09 30.82,15.09 35.03,19.29 35.03,19.64 34.66,20.01 33.49,20.01 32.85,19.38 32.85,18.56 30.39,16.1 26.58,16.1 26.35,16.33 22.79,16.33 19.36,19.76 13.17,19.76 12.48,19.07 12.48,18.03 12.74,17.78 19.37,17.78 22.85,14.3 25.21,14.3
VDD12_X1 on TOP: 18.87,9.66 14.12,9.66 13.8,9.35 12.86,9.35 12.67,9.54 12.67,10.68 12.78,10.78 13.54,10.78 14.29,11.53 18.73,11.53 18.96,11.3 18.96,9.75
VDD12_X2 on TOP: 18.84,7.12 15.49,7.12 15.44,7.17 15.44,7.5 15.55,7.6 16.03,7.6 16.23,7.8 16.23,8.28 16.37,8.42 18.84,8.42 18.99,8.28 18.99,7.26
C_PD_ADA_VBUS1 on TOP: 5.36,14.36 5.36,10.93 6.17,10.12 8.33,10.12 8.64,9.81 8.64,7.96 8.53,7.86 5.92,7.86 5.28,8.49 3.68,8.49 3.05,9.13 3.05,14.21 3.34,14.5 5.22,14.5
C_PD_ADA_VBUS1 on BOTTOM: 3.39,14.54 4.45,14.54 4.71,14.27 5.65,14.27 5.77,14.16 5.77,13.6 5.49,13.32 4.75,13.32 4.5,13.07 4.5,9.7 4.7,9.51 5.71,9.51 5.69,9.53 6.34,9.53 6.83,9.04 8.39,9.04 9.84,10.49 9.84,11.68 10.54,12.38 14.2,12.38 14.38,12.19 17.95,12.19 18.07,12.07 18.07,11.89 18.02,11.83 14.82,11.83 14.62,11.63 14.62,11.3 14.02,10.7 14.02,9 14.92,8.1 14.92,6.1 14.87,6.04 13.17,6.04 12.82,6.39 11.92,6.39 11.72,6.2 11.72,5.28 11.59,5.15 11.01,5.15 10.71,5.46 9.89,5.46 9.64,5.2 6.16,5.2 5.91,5.45 5.91,8.45 5.61,8.75 3.36,8.75 3.29,8.82 3.29,9.22 3.11,9.4 2.3,9.4 2.09,9.6 2.09,13.49 2.2,13.59 3.11,13.59 3.29,13.76 3.29,14.44
C_PD_ADA_VBUS1 on SIG3: 2.34,14.51 4.44,14.51 4.52,14.44 4.52,13.55 4.23,13.26 4,13.26 2.96,12.22 2.96,11.3 4.03,10.23 6.46,10.23 7.67,9.03 8.56,9.03 8.66,8.92 8.66,8.01 8.51,7.86 5.79,7.86 5.23,8.42 1.81,8.42 1.03,9.19 1.03,13.2
C_PD_ADA_VBUS1 on SIG4: 4.44,14.51 4.52,14.44 4.52,13.55 4.23,13.26 4,13.26 2.96,12.22 2.96,11.3 4.03,10.23 6.46,10.23 7.67,9.03 8.56,9.03 8.66,8.92 8.66,8.01 8.51,7.86 5.79,7.86 5.23,8.42 1.81,8.42 1.03,9.19 1.03,13.2 2.34,14.51
HV_AGND1 on BOTTOM: 41.22,14.68 41.22,13.87 41.11,13.87 40.92,14.05 39.71,14.05 39.55,13.89 39.55,13.65 39.5,13.6 37.69,13.6 37.64,13.65 37.64,14.97 39.14,16.46 39.44,16.46
HV_AGND1 on SIG3: 39.05,14.48 39.36,14.48 42.79,11.05 42.79,5.94 42.66,5.81 41.31,5.81 40.42,4.93 40.22,4.93 40.14,5 40.14,5.36 39.36,6.14 37.78,6.14 37.65,6.27 37.65,6.88 37.89,7.12 39.9,7.12 41.57,8.79 41.57,9.85 41.15,10.27 40.39,10.27 38.19,12.47 38.19,13.61
MOUT on BOTTOM: 18.29,12.81 19.92,12.81 22.24,10.5 22.24,9.75 22.81,9.18 22.81,3.74 22.76,3.69 22.53,3.69 22.43,3.79 22.43,6.66 22.28,6.82 21.62,6.82 21.39,6.58 20.45,6.58 20.05,6.98 19.25,6.98 18.32,6.04 16.98,6.04 16.88,6.14 16.88,8.93 17.94,9.99 17.94,11.48 18.22,11.76 18.22,12.16 18.12,12.27 14.49,12.27 14.39,12.37 14.39,12.49 14.48,12.58 18.06,12.58
MT7231_MOUT on BOTTOM: 23.27,8.24 23.27,3.79 23.16,3.69 22.99,3.69 22.94,3.74 22.94,7.91 22.59,8.25 22.59,10.03 22.67,10.11 22.95,10.11 23.08,9.98 24.17,9.98 24.22,9.92 24.22,9.2
PD_USP_VBUS on TOP: 39.33,21.33 42.35,21.33 42.89,20.8 42.89,16.13 42.81,16.05 42.81,14.45 42.68,14.32 42.56,14.32 42.48,14.4 42.48,15.61 42.25,15.83 41.45,15.83 41.29,15.67 39.79,15.67 39.15,16.3 39.15,21.16
PD_USP_VBUS_X1 on TOP: 39.23,15.57 39.56,15.24 41.22,15.24 41.57,15.59 42.15,15.59 42.25,15.49 42.25,13.79 41.49,13.02 41.49,12.8 41.49,10.13 41.41,10.06 38.77,10.06 38.52,10.31 38.52,12.82 38.28,13.07 30,13.07 29.88,13.18 29.88,14.03 30.62,14.77 30.62,15.26 30.92,15.57
PD_USP_VBUS_X1 on BOTTOM: 11.2,16.17 11.71,16.17 11.91,16.36 11.91,17.38 11.98,17.45 12.37,17.45 13.65,16.17 15.09,16.17 15.23,16.03 15.23,13.89 15.02,13.69 15.02,13.92 14.74,13.92 14.55,13.72 14.55,13.2 14.69,13.05 18.02,13.05 18.05,13.03 18.05,12.85 18.01,12.82 14.53,12.82 14.35,12.63 11.08,12.63 10.78,12.93 10.78,15.75
PD_USP_VBUS_X1 on SIG4: 29.12,10.18 15.02,10.18 12.69,12.52 12.69,15.22 12.9,15.43 16.04,15.43 18.26,13.21 27.9,13.21 29.17,14.48 31.2,14.48 31.63,14.04 31.63,12.7
PP5V0 on TOP: 30.48,21.19 32.13,21.19 32.21,21.12 32.21,19.85 32.38,19.67 32.43,19.67 33.15,18.96 33.15,16.85 33.09,16.79 30.47,16.79 30.21,17.04 30.21,20.93
PP5V0 on BOTTOM: 29.28,21.21 30.97,21.21 31.33,20.85 31.33,18.26 31.18,18.11 29.84,18.11 29.75,18.2 29.65,18.11 28.6,18.11 28.6,18.2 28.32,18.2 28.13,18.39 22.82,18.39 22.82,18.39 21.6,18.39 21.45,18.54 21.45,19.51 21.6,19.66 22.57,19.66 22.64,19.58 22.64,18.85 22.66,18.83 22.71,18.83 22.9,19.02 22.9,19.33 23.38,18.84 24.27,18.84 25.54,20.11 28.19,20.11
PP5V0 on SIG4: 22.74,20.19 26.58,20.19 26.76,20.01 26.76,18.54 26.64,18.43 22.99,18.43 22.52,18.9 22.52,19.96
PP5V0 on GND5: 25.44,19.84 26.28,19.84 26.76,19.35 26.76,18.79 26.64,18.68 25.73,18.68 25.34,19.07 25.34,19.73
PP5V0 on GND5: 22.52,19.99 23.2,19.99 23.33,19.86 23.33,19.25 23.25,19.17 22.95,19.17 22.69,18.92 21.58,18.92 21.5,19 21.5,19.76 21.6,19.86 22.39,19.86
PP5V0_SYS on TOP: 35.04,18.84 34.1,18.84 33.9,18.64 33.9,18.39 34.05,18.24 34.05,17 34.24,16.81 34.93,16.81 35.11,16.99 35.11,18.77
PP5V0_SYS on BOTTOM: 34.1,18.84 35.22,18.84 35.29,18.77 35.29,17.83 34.43,16.97 30.46,16.97 29.83,16.33 29.83,14.75 29.58,14.5 28.08,14.5 27.79,14.79 27.79,15.93 27.62,16.1 27.06,16.1 26.97,16.2 25.31,16.2 25.18,16.33 25.18,17.25 25.34,17.4 25.34,17.87 25.32,17.89 25.07,17.89 24.9,17.73 25.21,17.42 25.11,17.42 25.06,17.37 25.06,17.27 24.5,17.83 23.02,17.83 22.77,17.57 22.77,17.85 22.73,17.89 22.66,17.89 22.64,17.87 22.64,17.45 22.36,17.17 21.68,17.17 21.45,17.4 21.45,18.13 21.63,18.31 27.79,18.31 28.6,17.51 29.75,17.51 30.22,17.98 33.23,17.98
PP5V0_SYS on SIG4: 22.59,18.31 22.31,18.03 22.31,17.5 23.1,16.71 25.08,16.71 25.08,16.71 26.48,16.71 26.76,16.99 26.76,18.16 26.61,18.31
PP5V0_SYS on GND5: 21.83,18.31 23.71,18.31 23.79,18.24 23.79,17.52 23.66,17.4 21.75,17.4 21.65,17.5 21.65,18.13
PP5V0_SYS on GND5: 25.18,18.31 26.58,18.31 26.69,18.2 26.69,17.41 26.44,17.16 25.42,17.16 25.06,17.52 25.06,18.18
PW_5V_BST_SW1 on BOTTOM: 38.1,9.2 41.33,9.2 41.63,9.51 44.09,9.51 44.59,9.01 47.95,9.01 48.09,8.86 48.09,6.75 47.85,6.51 45.01,6.51 44.75,6.25 44.75,4.85 44.58,4.68 43.43,4.68 42.67,5.44 42.67,6.94 42.02,7.59 42.02,7.95 41.33,8.64 38.15,8.64 37.92,8.87 37.92,9.03
PW_5V_BST_SW2 on BOTTOM: 43.89,17.05 44.63,17.05 44.75,16.93 44.75,15.52 45.09,15.17 47.91,15.17 48.09,14.98 48.09,12.85 47.95,12.71 44.59,12.71 44.41,12.53 44.41,10.16 44.04,9.79 38.2,9.79 38.1,9.89 38.1,10.09 38.18,10.17 40.83,10.17 41.31,10.65 41.45,10.65 41.45,10.79 41.96,11.3 41.96,15.13
PW_5V_OUT on TOP: 29.55,12.52 37.86,12.52 37.96,12.42 37.96,11.63 37.83,11.5 29.58,11.5 29.43,11.66 29.43,12.39
PW_5V_OUT on BOTTOM: 36.1,13.8 38.48,11.41 40.51,11.41 40.57,11.35 40.57,11.1 40.61,11.1 40.72,11.21 41.33,10.6 41.33,10.47 41.13,10.28 38.16,10.28 37.95,10.07 36.14,10.07 36.07,10.14 36.07,10.55 35.47,11.15 30.97,11.15 30.97,11.15 29.22,11.15 29.15,11.22 29.15,12.7 30.25,13.8
PW_5V_OUT on GND2: 31.84,12.67 35.52,12.67 35.7,12.49 35.7,11.5 35.5,11.3 31.91,11.3 31.61,11.61 31.61,12.44
PW_5V_OUT on GND5: 31.91,12.49 34.66,12.49 34.78,12.37 34.78,11.25 34.71,11.17 31.84,11.17 31.76,11.25 31.76,12.34
PW_5V_VCC on BOTTOM: 39.81,13.55 40.79,13.55 40.89,13.44 41.4,13.44 41.78,13.06 41.78,11.67 41.5,11.39 40.79,11.39 40.61,11.57 40.61,12.48 40.44,12.66 39.93,12.66 39.67,12.91 39.67,13.41
PW_5V_VIN on TOP: 29.55,7.82 37.93,7.82 38.04,7.72 38.04,6.58 37.91,6.46 29.67,6.46 29.5,6.63 29.5,7.77
PW_5V_VIN on BOTTOM: 35.44,7.46 36.22,8.24 36.22,8.62 36.3,8.69 41.2,8.69 41.3,8.59 41.3,8.29 40.5,7.49 38.19,7.49 37.41,6.71 37.41,5.9 36.01,4.49 31.1,4.49 30.31,3.71 28.23,3.71 28,3.93 28,6.04 28.1,6.14 29.04,6.14 29.14,6.24 29.14,7.35 29.25,7.46
PW_5V_VIN on GND2: 31.58,7.21 35.19,7.21 35.34,7.36 35.34,7.97 34.84,8.48 31.84,8.48 31.41,8.05 31.41,7.39
PW_5V_VIN on GND5: 31.79,8.48 34.84,8.48 35.19,8.13 35.19,7.03 35.14,6.98 31.49,6.98 31.43,7.03 31.43,8.13
N17338285 on BOTTOM: 47.07,17.08 48.34,17.08 48.57,16.85 48.57,15.53 48.34,15.3 47.12,15.3 46.96,15.45 46.96,16.98
N17338604 on BOTTOM: 30.69,16.84 33.64,16.84 33.87,16.61 33.87,14.63 33.44,14.2 31,14.2 30.46,14.74 30.46,16.6
N17399398 on BOTTOM: 24.66,12.15 25.33,12.15 25.49,11.99 25.49,10.49 25.47,10.47 24.59,10.47 24.48,10.58 24.48,11.97
N17404682 on BOTTOM: 10.4,18.08 10.81,18.08 11.42,17.47 11.42,16.51 11.31,16.41 10.73,16.41 10.53,16.61 10.53,17.5 10.32,17.7 10.32,18.01
N17484520 on BOTTOM: 12.2,6.09 12.94,6.09 13.5,5.54 13.5,5.13 13.32,4.95 12.31,4.95 12.18,5.08 12.18,6.07
N17796413 on BOTTOM: 31.94,21.05 33.03,21.05 33.16,20.93 33.16,20.04 32.88,19.76 31.99,19.76 31.84,19.91 31.84,20.95
N17839235 on TOP: 43.52,15.11 44.33,15.11 44.89,14.56 45.32,14.56 45.48,14.4 45.48,13.92 45.33,13.77 44.18,13.77 43.42,14.53 43.42,15.01
N17894716 on BOTTOM: 47.07,6.28 48.34,6.28 48.57,6.05 48.57,4.74 48.34,4.5 47.12,4.5 46.96,4.66 46.96,6.18

Small or netless copper shapes (teardrops, artwork), in the pictures only: 1 on GND5

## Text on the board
Ref Des/Silkscreen Top: BM01-PB-V0.4HF | 2026-09-15
DXF_0710: COPIED OR CUED IN ANY MANNER | AND SHALL NOT BE REPRODUCED, | WITHOUT THE PRIOR WRITTEN CONSENT | OF LUXSHARE-ICT | THESE DRAWINGS AND SPECIFICATIONS | ARE THE PROPERTY OF LUXSHARE-ICT | X | UNITS: | mm | PART NO.: | TITLE: | APPD: | CHKD: | DRAW: | XXXXXX | PCB | DWG NO: | SUPPLIER P/N: | \ | SCALE | 1:1 | SHEET | 1/1 | REV. | X1 | HF
User.8: X | COPIED OR CUED IN ANY MANNER | AND SHALL NOT BE REPRODUCED, | WITHOUT THE PRIOR WRITTEN CONSENT | OF LUXSHARE-ICT | THESE DRAWINGS AND SPECIFICATIONS | ARE THE PROPERTY OF LUXSHARE-ICT | UNITS: | mm | PART NO.: | TITLE: | APPD: | CHKD: | DRAW: | DWG NO: | SUPPLIER P/N: | SCALE | SHEET | REV. | XXXXXX | PD PCB | \ | 1:1 | 1/1 | X1 | HF
User.9: X | COPIED OR CUED IN ANY MANNER | AND SHALL NOT BE REPRODUCED, | WITHOUT THE PRIOR WRITTEN CONSENT | OF LUXSHARE-ICT | THESE DRAWINGS AND SPECIFICATIONS | ARE THE PROPERTY OF LUXSHARE-ICT | UNITS: | mm | PART NO.: | TITLE: | APPD: | CHKD: | DRAW: | DWG NO: | SUPPLIER P/N: | SCALE | SHEET | REV. | XXXXXX | PD PCB | \ | 1:1 | 1/1 | X1 | HF
User.22: + | 3 | 1 | A | D
User.23: + | D | A | 1 | 3
User.24: + | 2 | 4 | 1 | {\Fromans,@extfont2|c134;4.00%%P0.10} | {\Fromans,@extfont2|c134;2.30%%P0.15} | {\Fromans,@extfont2|c134;1.00%%P0.10} | {\Fromans,@extfont2|c134;3.43%%P0.10} | BM01-PB-V0.2HF | 2026-01-28 | A
User.25: + | 2 | 4 | 1 | {\Fromans,@extfont2|c134;4.00%%P0.10} | {\Fromans,@extfont2|c134;2.30%%P0.15} | {\Fromans,@extfont2|c134;1.00%%P0.10} | {\Fromans,@extfont2|c134;3.43%%P0.10} | A
User.26: + | 3 | 2 | 4 | 1 | {\Fromans,@extfont2|c134;59.48%%P0.10} | {\Fromans,@extfont2|c134;57.54%%P0.20} | {\Fromans,@extfont2|c134;23.00%%P0.15} | {\Fromans,@extfont2|c134;4.00%%P0.10} | {\Fromans,@extfont2|c134;2.30%%P0.15} | {\Fromans,@extfont2|c134;1.00%%P0.10} | {\Fromans,@extfont2|c134;3.43%%P0.10} | BM01-PB-V0.2HF | 2026-01-28 | A
User.27: + | 2 | 4 | 1 | {\Fromans,@extfont2|c134;4.00%%P0.10} | {\Fromans,@extfont2|c134;2.30%%P0.15} | {\Fromans,@extfont2|c134;1.00%%P0.10} | {\Fromans,@extfont2|c134;3.43%%P0.10} | A
User.28: BM01-PB-V0.2HF | 2026-01-30 | A | 1
User.29: A | 1
User.34: FIGURE | FINISHED_SIZE | 8.0 | 12.0 | 86.61 | 125.98 | 23.62 | 45.28x19.69 | 51.18x19.69 | 141.73x23.62 | DRILL CHART: TOP to BOTTOM | ALL UNITS ARE IN MILS | TOLERANCE_DRILL | +3.0/-3.0 | +0.0/-0.0 | PLATED | NON-PLATED | QTY | 111 | 178 | 2 | 6 | 4
User.35: FIGURE | FINISHED_SIZE | 3.94 | DRILL CHART: TOP to GND2 | ALL UNITS ARE IN MILS | TOLERANCE_DRILL | +0.0/-0.0 | PLATED | QTY | 562
User.36: FIGURE | FINISHED_SIZE | 8.0 | DRILL CHART: GND2 to GND5 | ALL UNITS ARE IN MILS | TOLERANCE_DRILL | +0.0/-0.0 | PLATED | QTY | 432
User.37: FIGURE | FINISHED_SIZE | 3.94 | DRILL CHART: GND5 to BOTTOM | ALL UNITS ARE IN MILS | TOLERANCE_DRILL | +0.0/-0.0 | PLATED | QTY | 654
